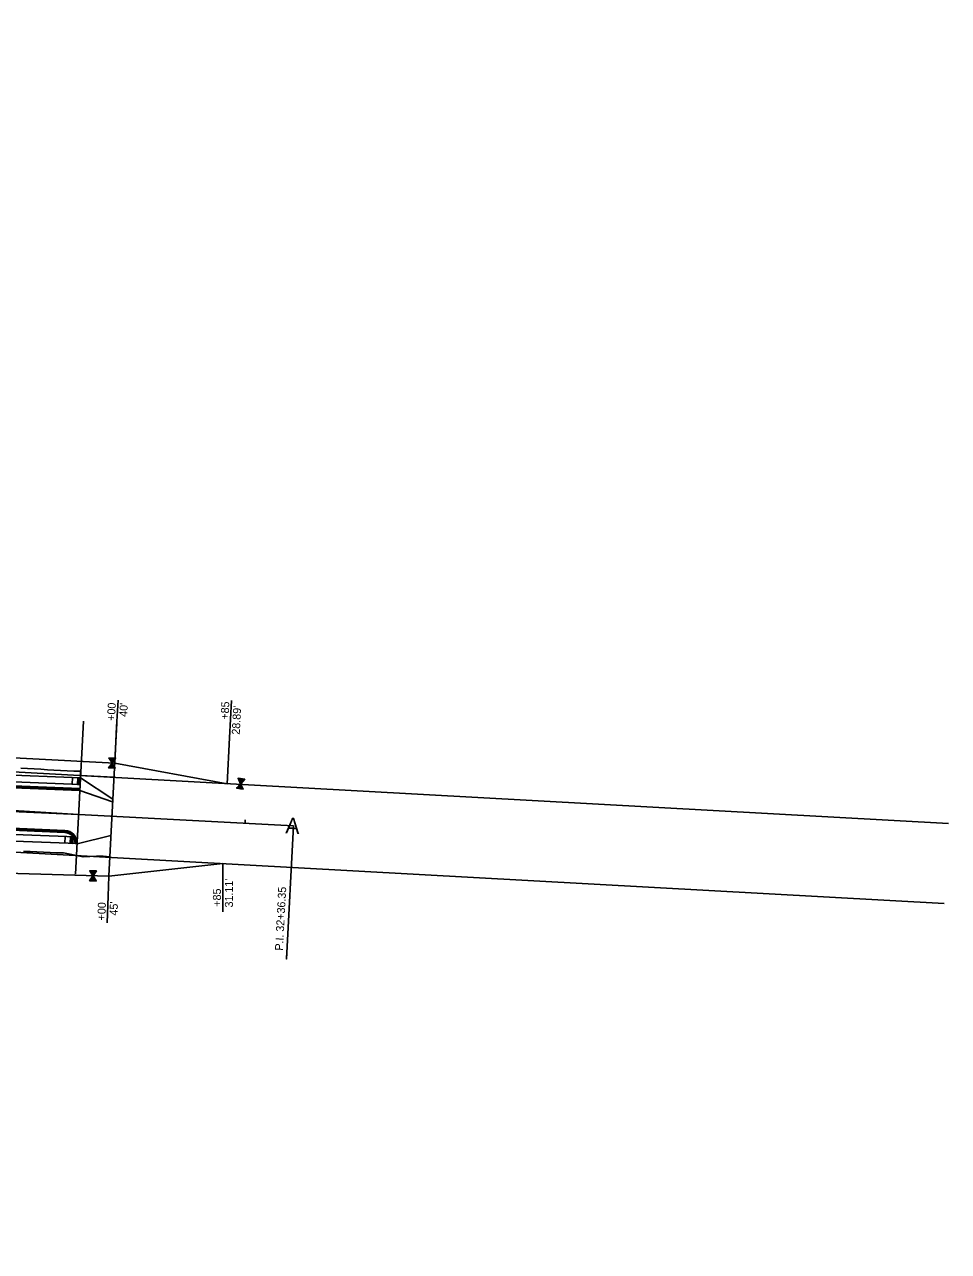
# Model space of a CAD drawing. Extents: x 670017 to 673226, y 705371 to 707498.
# Drawn here: x 672533 to 673226, y 706170 to 707090 of the extents above; entities that cross this region are included whole.
import ezdxf

# ---------------------------------------------------------------- set-up
doc = ezdxf.new("R2010")
doc.units = 0
for name, color, linetype in [('EL L 264', 7, 'Continuous'), ('EL R 264', 7, 'Continuous'), ('R_Fence', 7, 'Continuous'), ('R_Horz Alg', 7, 'Continuous'), ('R_Horz Alg Station', 7, 'Continuous'), ('R_Horz Alg Station Annot', 7, 'Continuous'), ('R_No Plot', 7, 'Continuous'), ('R_No Plot FOC', 7, 'Continuous'), ('R_Proposed Const Limits', 7, 'Continuous'), ('R_Proposed Const Limits Stage 2', 7, 'Continuous'), ('R_Proposed Road', 7, 'Continuous'), ('R_Proposed Road Stage 2', 7, 'Continuous'), ('R_Proposed Shoulder Stage 1', 7, 'Continuous'), ('R_Proposed Sidewalk Stage 1', 7, 'Continuous'), ('R_Proposed Sidewalk Stage 2', 7, 'Continuous'), ('R_ROW', 7, 'Continuous'), ('R_ROW Annot', 7, 'Continuous'), ('R_Striping', 7, 'Continuous'), ('S_EXIST_ROW', 7, 'Continuous')]:
    doc.layers.add(name, color=color, linetype=linetype)

msp = doc.modelspace()

# ---------------------------------------------------------------- linework, layer by layer
at = {"layer": 'EL L 264'}
msp.add_line((672366.78, 706523.88), (672574.61, 706515.27), dxfattribs=at)
msp.add_line((672366.78, 706523.88), (672574.61, 706515.27), dxfattribs=at)
at = {"layer": 'EL R 264'}
msp.add_line((672187.89, 706500.52), (672563.37, 706485.4), dxfattribs=at)
msp.add_arc((672563.03, 706475.9), 9.5, 356.99576, 87.93569, dxfattribs=at)
at = {"layer": 'R_Fence'}
for p, q in [((672596.83, 706539.75), (672596.56, 706539.49)), ((672597.54, 706539.72), (672596.83, 706539.06)), ((672598.25, 706539.7), (672597.1, 706538.62)), ((672598.95, 706539.68), (672597.37, 706538.19)), ((672599.66, 706539.66), (672597.64, 706537.76)), ((672600.37, 706539.64), (672597.91, 706537.33)), ((672601.07, 706539.62), (672598.18, 706536.89)), ((672599.26, 706535.16), (672596.18, 706532.26)), ((672599.53, 706534.73), (672596.89, 706532.24)), ((672599.8, 706534.3), (672597.6, 706532.22)), ((672598.99, 706535.6), (672597.62, 706534.31)), ((672600.07, 706533.87), (672598.3, 706532.2)), ((672600.58, 706538.46), (672598.45, 706536.46)), ((672599.1, 706536.39), (672598.72, 706536.03)), ((672600.34, 706533.43), (672599.01, 706532.18)), ((672600.61, 706533), (672599.72, 706532.16)), ((672600.88, 706532.57), (672600.42, 706532.14)), ((672601.15, 706532.14), (672601.13, 706532.11)), ((672693.75, 706524.43), (672693.45, 706524.21)), ((672694.45, 706524.31), (672693.66, 706523.74)), ((672695.14, 706524.2), (672693.87, 706523.28)), ((672695.84, 706524.09), (672694.08, 706522.82)), ((672696.54, 706523.97), (672694.29, 706522.35)), ((672697.24, 706523.86), (672694.5, 706521.89)), ((672697.94, 706523.75), (672694.71, 706521.42)), ((672697.29, 706522.67), (672694.92, 706520.96)), ((672695.56, 706520.8), (672695.14, 706520.5)), ((672695.56, 706519.57), (672692.12, 706517.09)), ((672695.77, 706519.1), (672692.82, 706516.98)), ((672695.98, 706518.64), (672693.52, 706516.87)), ((672695.35, 706520.03), (672693.82, 706518.93)), ((672696.19, 706518.18), (672694.22, 706516.75)), ((672696.4, 706517.71), (672694.92, 706516.64)), ((672696.61, 706517.25), (672695.61, 706516.53)), ((672696.82, 706516.78), (672696.31, 706516.41)), ((672697.04, 706516.32), (672697.01, 706516.3)), ((672584.96, 706450.61), (672581.88, 706447.71)), ((672582.53, 706455.19), (672582.26, 706454.94)), ((672583.24, 706455.17), (672582.53, 706454.51)), ((672585.23, 706450.18), (672582.59, 706447.69)), ((672583.94, 706455.15), (672582.8, 706454.07)), ((672584.65, 706455.13), (672583.07, 706453.64)), ((672585.5, 706449.75), (672583.29, 706447.67)), ((672584.69, 706451.05), (672583.32, 706449.75)), ((672585.36, 706455.11), (672583.34, 706453.21)), ((672586.06, 706455.09), (672583.61, 706452.78)), ((672586.77, 706455.07), (672583.88, 706452.34)), ((672585.77, 706449.32), (672584, 706447.65)), ((672586.27, 706453.91), (672584.15, 706451.91)), ((672584.8, 706451.83), (672584.42, 706451.48)), ((672586.04, 706448.88), (672584.71, 706447.63)), ((672586.31, 706448.45), (672585.41, 706447.61)), ((672586.58, 706448.02), (672586.12, 706447.58)), ((672586.85, 706447.59), (672586.83, 706447.56))]:
    msp.add_line(p, q, dxfattribs=at)
for points in [[(672598.79, 706535.93), (672598.79, 706535.94), (672601.39, 706539.61), (672596.39, 706539.76), (672598.78, 706535.94), (672598.78, 706535.93), (672596.17, 706532.26), (672601.17, 706532.11), (672598.79, 706535.93)], [(672695.18, 706520.39), (672695.19, 706520.4), (672698.25, 706523.7), (672693.31, 706524.5), (672695.18, 706520.4), (672695.18, 706520.39), (672692.11, 706517.09), (672697.05, 706516.29), (672695.18, 706520.39)], [(672584.48, 706451.38), (672584.48, 706451.39), (672587.09, 706455.06), (672582.09, 706455.21), (672584.47, 706451.39), (672584.47, 706451.38), (672581.87, 706447.71), (672586.86, 706447.56), (672584.48, 706451.38)]]:
    msp.add_lwpolyline(points, dxfattribs=at)
at = {"layer": 'R_Horz Alg'}
msp.add_line((670501.52, 706606.05), (672734.79, 706488.84), dxfattribs=at)
at = {"layer": 'R_Horz Alg Station'}
for points in [[(672598.77, 706498.48), (672598.63, 706495.99)], [(672698.63, 706493.24), (672698.5, 706490.74)], [(672734.79, 706488.84), (672729.55, 706388.98), (672729.87, 706394.97)]]:
    msp.add_lwpolyline(points, dxfattribs=at)
at = {"layer": 'R_No Plot'}
for p, q in [((672577.34, 706567.21), (672571.33, 706452.7)), ((672602.3, 706565.9), (672596.29, 706451.39)), ((672685.03, 706520.38), (672600.73, 706535.93)), ((672596.28, 706451.05), (672681.89, 706460.47))]:
    msp.add_line(p, q, dxfattribs=at)
msp.add_lwpolyline([(672600.73, 706535.93), (672600.73, 706535.93), (672146.36, 706559.78), (671852.81, 706595.21), (671791.92, 706679.49), (671797.39, 707089.58)], dxfattribs=at)
at = {"layer": 'R_No Plot FOC'}
for p, q in [((672366.83, 706524.88), (672574.65, 706516.27)), ((672187.85, 706499.52), (672563.33, 706484.4))]:
    msp.add_line(p, q, dxfattribs=at)
msp.add_arc((672563.03, 706475.9), 8.5, 356.99576, 87.93569, dxfattribs=at)
at = {"layer": 'R_Proposed Const Limits'}
msp.add_lwpolyline([(672530.27, 706532.12), (672535.26, 706531.81), (672540.25, 706531.51), (672545.24, 706531.2), (672550.24, 706530.9), (672555.23, 706530.59), (672560.22, 706530.28), (672565.21, 706529.96), (672570.21, 706529.75), (672575.21, 706529.75), (672575.21, 706526.58), (672580.2, 706526.31), (672585.19, 706526.04), (672590.18, 706525.76), (672595.18, 706525.49), (672600.17, 706525.22)], dxfattribs=at)
at = {"layer": 'R_Proposed Const Limits Stage 2'}
msp.add_lwpolyline([(672532.37, 706469.7), (672537.37, 706469.49), (672542.36, 706469.29), (672547.36, 706469.08), (672552.36, 706468.87), (672557.35, 706468.67), (672562.35, 706468.47), (672577, 706465.46), (672582.03, 706465.74), (672587.05, 706466.03), (672592.05, 706466.02), (672597.04, 706465.62)], dxfattribs=at)
at = {"layer": 'R_Proposed Road'}
for p, q in [((672366.78, 706523.88), (672574.61, 706515.27)), ((672366.86, 706525.38), (672574.67, 706516.77)), ((672574.61, 706515.27), (672599.2, 706506.78))]:
    msp.add_line(p, q, dxfattribs=at)
at = {"layer": 'R_Proposed Road Stage 2'}
for p, q in [((672187.83, 706499.02), (672563.31, 706483.9)), ((672187.89, 706500.52), (672563.37, 706485.4)), ((672571.02, 706475.48), (672572.52, 706475.41)), ((672572.52, 706475.41), (672597.88, 706481.63))]:
    msp.add_line(p, q, dxfattribs=at)
for radius in [8, 9.5]:
    msp.add_arc((672563.03, 706475.9), radius, 356.99576, 87.93569, dxfattribs=at)
at = {"layer": 'R_Proposed Shoulder Stage 1'}
msp.add_line((672575, 706524.76), (672599.31, 706508.78), dxfattribs=at)
at = {"layer": 'R_Proposed Sidewalk Stage 1'}
for p, q in [((672367.19, 706533.37), (672575, 706524.76)), ((672366.98, 706528.37), (672574.8, 706519.77)), ((672569.01, 706525.01), (672568.8, 706520.02)), ((672575, 706524.76), (672574.8, 706519.77))]:
    msp.add_line(p, q, dxfattribs=at)
msp.add_lwpolyline([(672572.8, 706519.85), (672573.01, 706524.85), (672575, 706524.76), (672574.8, 706519.77)], close=True, dxfattribs=at)
for centre in [(672573.22, 706520.23), (672573.24, 706520.83), (672573.26, 706521.43), (672573.29, 706522.03), (672573.31, 706522.63), (672573.34, 706523.23), (672573.36, 706523.83), (672573.39, 706524.43), (672573.81, 706520.21), (672573.84, 706520.81), (672573.86, 706521.41), (672573.89, 706522.01), (672573.91, 706522.61), (672573.94, 706523.21), (672573.96, 706523.8), (672573.99, 706524.4), (672574.41, 706520.18), (672574.44, 706520.78), (672574.46, 706521.38), (672574.49, 706521.98), (672574.51, 706522.58), (672574.54, 706523.18), (672574.56, 706523.78), (672574.59, 706524.38)]:
    msp.add_circle(centre, 0.165, dxfattribs=at)
at = {"layer": 'R_Proposed Sidewalk Stage 2'}
for p, q in [((672187.68, 706496.02), (672571.31, 706480.57)), ((672187.45, 706491.03), (672572.53, 706475.52)), ((672563.48, 706480.89), (672563.28, 706475.89)), ((672567.48, 706480.73), (672567.27, 706475.73))]:
    msp.add_line(p, q, dxfattribs=at)
msp.add_lwpolyline([(672569.47, 706480.65), (672569.27, 706475.65), (672567.27, 706475.73), (672567.48, 706480.73)], close=True, dxfattribs=at)
for centre in [(672567.69, 706476.12), (672567.71, 706476.72), (672567.74, 706477.32), (672567.76, 706477.91), (672567.79, 706478.51), (672567.81, 706479.11), (672567.84, 706479.71), (672567.86, 706480.31), (672568.29, 706476.09), (672568.31, 706476.69), (672568.34, 706477.29), (672568.36, 706477.89), (672568.39, 706478.49), (672568.41, 706479.09), (672568.43, 706479.69), (672568.46, 706480.29), (672568.89, 706476.07), (672568.91, 706476.67), (672568.94, 706477.27), (672568.96, 706477.87), (672568.99, 706478.47), (672569.01, 706479.07), (672569.03, 706479.66), (672569.06, 706480.26)]:
    msp.add_circle(centre, 0.165, dxfattribs=at)
at = {"layer": 'R_ROW'}
for p, q in [((672685.03, 706520.38), (672600.73, 706535.93)), ((672596.28, 706451.05), (672681.89, 706460.47))]:
    msp.add_line(p, q, dxfattribs=at)
for points in [[(672600.73, 706535.93), (672600.73, 706535.93), (672146.36, 706559.78), (671852.81, 706595.21), (671791.92, 706679.49), (671797.39, 707089.58)], [(672596.28, 706451.05), (672596.28, 706451.05), (672161.7, 706463.84), (671891.46, 706473.02), (671825.24, 706451.46), (671776.29, 706399.8), (671754.1, 706085.43), (671832.11, 706032.37), (671817.47, 705912.84), (671726.19, 705881.35)]]:
    msp.add_lwpolyline(points, dxfattribs=at)
at = {"layer": 'R_ROW Annot'}
for points in [[(672600.73, 706535.93), (672602.17, 706563.01), (672603.23, 706582.98)], [(672685.03, 706520.38), (672686.81, 706554.88), (672688.28, 706582.84)], [(672681.89, 706460.47), (672681.89, 706445.47), (672681.89, 706424.23)], [(672596.28, 706451.05), (672595.81, 706436.05), (672595.18, 706416.06)]]:
    msp.add_lwpolyline(points, dxfattribs=at)
at = {"layer": 'R_Striping'}
for p, q in [((672189.02, 706521.63), (672573.67, 706497.3)), ((672573.67, 706497.3), (672187.71, 706514.55))]:
    msp.add_line(p, q, dxfattribs=at)
at = {"layer": 'S_EXIST_ROW'}
for points in [[(670020.59, 706668.53), (670619.99, 706639.58), (670619.86, 706634.58), (671728.16, 706573.3), (673225.88, 706490.48)], [(670017.21, 706598.61), (670616.41, 706569.67), (670616.54, 706574.67), (671724.85, 706513.39), (673222.56, 706430.57)]]:
    msp.add_lwpolyline(points, dxfattribs=at)

# ---------------------------------------------------------------- texts
at = {"layer": 'R_Horz Alg'}
msp.add_text('A', height=12, rotation=356.99576, dxfattribs=at).set_placement((672728.49, 706483.16))
at = {"layer": 'R_Horz Alg Station Annot'}
msp.add_text('P.I. 32+36.35', height=6, rotation=86.99576, dxfattribs=at).set_placement((672726.87, 706395.13))
at = {"layer": 'R_ROW Annot'}
for s, rotation, p in [('+00', 86.96365, (672600.9, 706567.43)), ("40'", 86.96365, (672610.07, 706570.41)), ('+85', 86.97801, (672686.05, 706568.29)), ("28.89'", 86.97801, (672694.47, 706557.05)), ("31.11'", 90, (672689.39, 706427.63)), ('+85', 90, (672680.39, 706428.2)), ('+00', 88.20317, (672593.73, 706417.85)), ("45'", 88.20317, (672602.85, 706421.49))]:
    msp.add_text(s, height=6, rotation=rotation, dxfattribs=at).set_placement(p)

doc.saveas('drawing.dxf')
